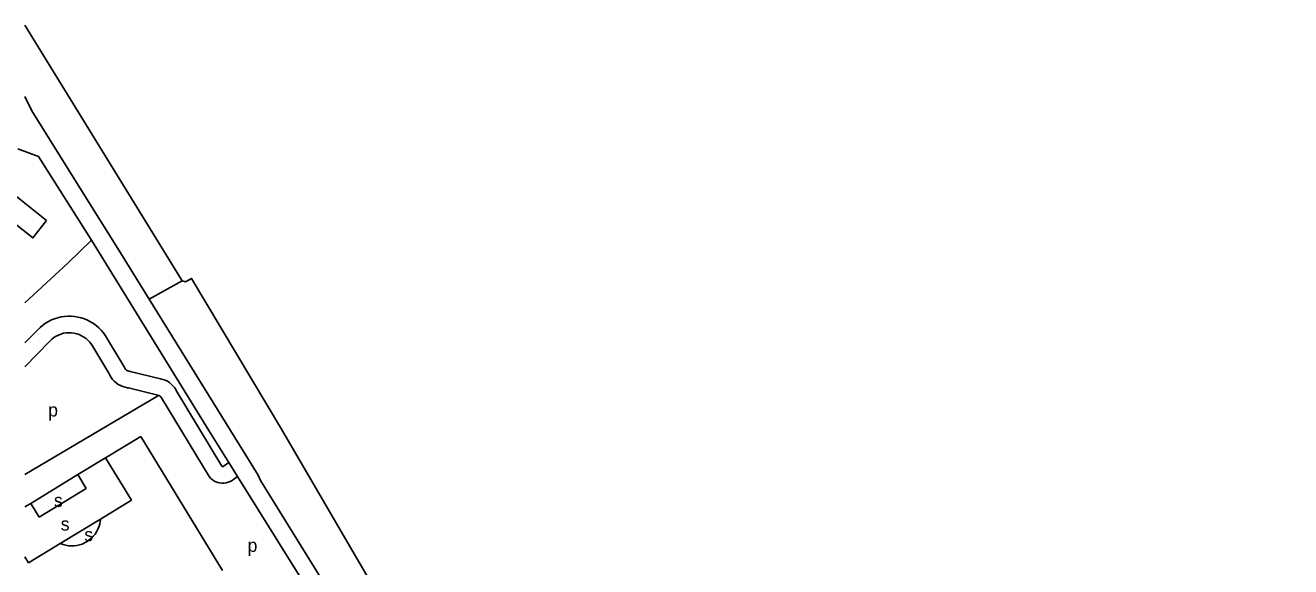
# Model space of a CAD drawing. Extents: x 156721 to 158827, y 386657 to 388950.
# Drawn here: x 158050.1 to 158433.3, y 388308.1 to 388471.8 of the extents above; entities that cross this region are included whole.
import ezdxf

# ---------------------------------------------------------------- set-up
doc = ezdxf.new("R2010")
doc.units = 0
for name, color, linetype in [('BLT_Basislijn', 7, 'Continuous'), ('BLT_Bebouwing', 7, 'Continuous'), ('BLT_Centroide', 7, 'Continuous'), ('BLT_Vlakafsluiter', 7, 'Continuous')]:
    doc.layers.add(name, color=color, linetype=linetype)

msp = doc.modelspace()

# ---------------------------------------------------------------- linework, layer by layer
at = {"layer": 'BLT_Basislijn'}
for p, q in [((158054.07, 388432.16), (158047.83, 388434.46)), ((158070.12, 388406.85), (158054.07, 388432.16)), ((158068.65, 388419.47), (158077.59, 388405.14)), ((158105.72, 388349.24), (158070.12, 388406.85)), ((158053.89, 388379.75), (158050, 388375.75)), ((158074.4, 388377.94), (158080, 388368.5)), ((158050, 388368.56), (158057.52, 388376.31)), ((158075.35, 388366.65), (158070.21, 388375.19)), ((158091.08, 388364.86), (158081.82, 388367.13)), ((158081.34, 388362.16), (158090.25, 388359.93)), ((158109.64, 388338.5), (158095.82, 388361.38)), ((158050, 388335.95), (158090.42, 388359.89)), ((158091.36, 388359.11), (158105.77, 388335.32)), ((158085.07, 388347.5), (158074.4, 388341)), ((158085.07, 388347.5), (158109.77, 388306.92)), ((158105.72, 388349.24), (158111.72, 388339.61)), ((158074.4, 388341), (158066.03, 388335.91)), ((158074.4, 388341), (158082.21, 388328.16)), ((158110.06, 388338.39), (158111.72, 388339.61)), ((158111.72, 388339.61), (158114.39, 388335.33)), ((158066.03, 388335.91), (158051.74, 388327.21)), ((158066.03, 388335.91), (158068.58, 388331.71)), ((158113.25, 388334.54), (158114.39, 388335.33)), ((158054.29, 388323.01), (158068.58, 388331.71)), ((158051.74, 388327.21), (158050, 388326.15)), ((158051.74, 388327.21), (158054.29, 388323.01)), ((158072.9, 388322.49), (158082.21, 388328.16)), ((158060.69, 388315.06), (158072.9, 388322.49)), ((158051.11, 388309.22), (158060.69, 388315.06)), ((158050, 388311.04), (158051.11, 388309.22))]:
    msp.add_line(p, q, dxfattribs=at)
for points in [[(158050, 388471.85), (158097.61, 388394.52)], [(158050, 388450.29), (158052.1, 388446.01), (158068.65, 388419.47)], [(158050, 388387.9), (158063.02, 388399.89), (158070.12, 388406.85)], [(158077.59, 388405.14), (158087.6, 388388.98)], [(158097.61, 388394.52), (158098.6, 388394.27), (158100.46, 388395.24)], [(158100.57, 388395.31), (158100.46, 388395.24)], [(158100.46, 388395.24), (158127.66, 388349.71), (158157.43, 388298.63), (158170.49, 388277.72)], [(158087.6, 388388.98), (158120.58, 388335.72), (158121.32, 388334.13), (158168.5, 388258.11), (158180.9, 388237.55), (158193.49, 388217.63), (158243.23, 388136.8), (158258.3, 388113.07), (158338.44, 387984.38), (158433.27, 387830.65)], [(158053.89, 388379.75), (158054.62, 388380.47), (158055.41, 388381.12), (158056.24, 388381.72), (158057.12, 388382.24), (158058.04, 388382.7), (158058.99, 388383.08), (158059.96, 388383.39), (158060.96, 388383.62), (158061.98, 388383.78), (158063, 388383.85), (158064.02, 388383.84), (158065.04, 388383.76), (158066.05, 388383.59), (158067.05, 388383.35), (158068.02, 388383.03), (158068.96, 388382.63), (158069.88, 388382.16), (158070.75, 388381.62), (158071.58, 388381.02), (158072.35, 388380.35), (158073.08, 388379.63), (158073.74, 388378.85), (158074.4, 388377.94)], [(158057.52, 388376.31), (158058.11, 388376.87), (158058.74, 388377.37), (158059.42, 388377.8), (158060.14, 388378.16), (158060.89, 388378.45), (158061.67, 388378.67), (158062.46, 388378.8), (158063.27, 388378.86), (158064.07, 388378.83), (158064.87, 388378.73), (158065.66, 388378.55), (158066.42, 388378.29), (158067.15, 388377.95), (158067.85, 388377.55), (158068.5, 388377.07), (158069.11, 388376.54), (158069.65, 388375.95), (158070.14, 388375.31), (158070.21, 388375.19)], [(158075.35, 388366.65), (158075.67, 388365.96), (158076.06, 388365.31), (158076.52, 388364.7), (158077.03, 388364.15), (158077.6, 388363.65), (158078.23, 388363.22), (158078.89, 388362.85), (158079.59, 388362.55), (158080.31, 388362.33), (158081.06, 388362.19), (158081.34, 388362.16)], [(158080, 388368.5), (158080.19, 388368.13), (158080.45, 388367.8), (158080.76, 388367.53), (158081.13, 388367.32), (158081.52, 388367.18), (158081.82, 388367.13)], [(158091.08, 388364.86), (158091.78, 388364.7), (158092.46, 388364.47), (158093.12, 388364.16), (158093.73, 388363.78), (158094.3, 388363.33), (158094.82, 388362.83), (158095.28, 388362.27), (158095.67, 388361.66), (158095.82, 388361.38)], [(158090.25, 388359.93), (158090.42, 388359.89)], [(158090.42, 388359.89), (158090.58, 388359.84), (158090.89, 388359.67), (158091.15, 388359.43), (158091.36, 388359.11)], [(158110.06, 388338.39), (158109.93, 388338.33), (158109.79, 388338.35), (158109.64, 388338.5)], [(158113.25, 388334.54), (158112.73, 388334.16), (158112.16, 388333.84), (158111.56, 388333.6), (158110.93, 388333.43), (158110.29, 388333.34), (158109.64, 388333.33), (158108.99, 388333.4), (158108.36, 388333.55), (158107.76, 388333.78), (158107.18, 388334.08), (158106.65, 388334.45), (158106.16, 388334.88), (158105.77, 388335.32)], [(158114.39, 388335.33), (158139.24, 388295.45), (158153.82, 388271.51)], [(158060.69, 388315.06), (158061.54, 388314.74), (158062.35, 388314.53), (158063.18, 388314.4), (158064.01, 388314.35), (158064.85, 388314.37), (158065.68, 388314.48), (158066.49, 388314.67), (158067.29, 388314.93), (158068.06, 388315.26), (158068.79, 388315.67), (158069.47, 388316.15), (158070.11, 388316.69), (158070.7, 388317.29), (158071.22, 388317.94), (158071.68, 388318.64), (158072.08, 388319.38), (158072.4, 388320.15), (158072.64, 388320.95), (158072.81, 388321.77), (158072.9, 388322.49)]]:
    msp.add_lwpolyline(points, dxfattribs=at)
at = {"layer": 'BLT_Bebouwing'}
msp.add_lwpolyline([(158056.56, 388412.78), (158045.96, 388421.28), (158041.71, 388418.43), (158040.87, 388419.11), (158031.86, 388413.08), (158029.01, 388417.18), (158024.19, 388413.96), (158026.97, 388409.81), (158025.09, 388408.56), (158029, 388402.74), (158029.76, 388403.23), (158029.21, 388404.08), (158044.14, 388414.08), (158052.39, 388407.54)], close=True, dxfattribs=at)
at = {"layer": 'BLT_Vlakafsluiter'}
msp.add_line((158097.61, 388394.52), (158087.6, 388388.98), dxfattribs=at)

# ---------------------------------------------------------------- texts
at = {"layer": 'BLT_Centroide'}
for s, p in [('p', (158057.02, 388353.5)), ('s', (158058.77, 388326.12)), ('s', (158060.83, 388319)), ('s', (158067.96, 388315.78)), ('p', (158117.4, 388312.54))]:
    msp.add_text(s, height=4, dxfattribs=at).set_placement(p)

doc.saveas('drawing.dxf')
